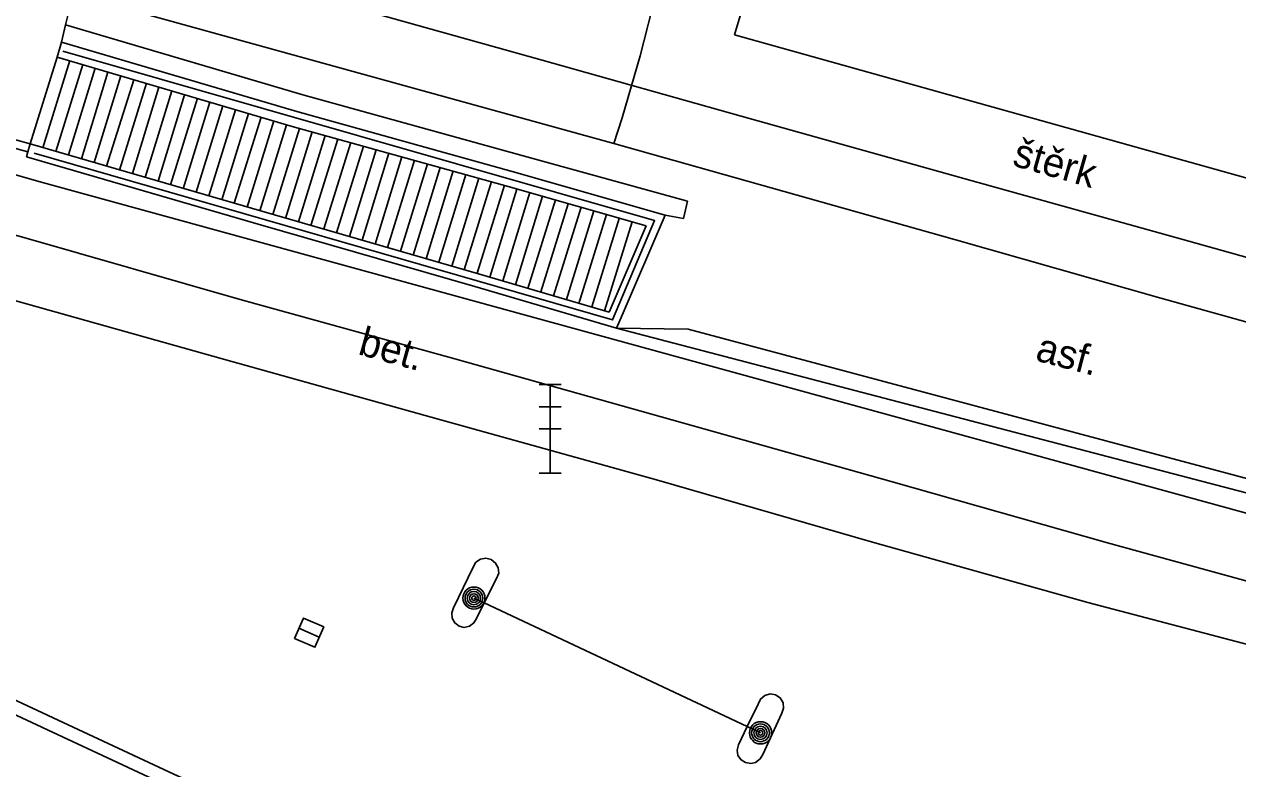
# Model space of a CAD drawing. Extents: x -600309 to -598967, y -1161267 to -1160292.
# Drawn here: x -599876.57 to -599849.18, y -1161220.83 to -1161204.03 of the extents above; entities that cross this region are included whole.
import ezdxf

# ---------------------------------------------------------------- set-up
doc = ezdxf.new("R2010")
doc.units = 0
for name, color, linetype in [('Level 11', 7, 'Continuous'), ('Level 13', 7, 'Continuous'), ('Level 25', 7, 'Continuous'), ('Level 27', 7, 'Continuous'), ('Level 33', 7, 'Continuous'), ('Level 40', 7, 'Continuous'), ('Level 7', 7, 'Continuous'), ('Level 9', 7, 'Continuous')]:
    doc.layers.add(name, color=color, linetype=linetype)

msp = doc.modelspace()

# ---------------------------------------------------------------- linework, layer by layer
at = {"layer": 'Level 11'}
for points in [[(-599943.57, -1161188.06), (-599943.4099, -1161188.13), (-599934.69, -1161190.53), (-599924.78, -1161193.29), (-599915.04, -1161195.99), (-599905.21, -1161198.73), (-599895.46, -1161201.46), (-599885.6599, -1161204.19), (-599876.44, -1161206.73)], [(-599943.62, -1161188.24), (-599939.48, -1161189.38), (-599934.7199, -1161190.69), (-599929.63, -1161192.12), (-599924.84, -1161193.46), (-599919.9, -1161194.81), (-599915.13, -1161196.14), (-599910.12, -1161197.53), (-599905.29, -1161198.87), (-599900.4099, -1161200.24), (-599895.52, -1161201.62), (-599891.36, -1161202.78), (-599885.75, -1161204.34), (-599880.31, -1161205.86), (-599876.49, -1161206.9099)], [(-599789.95, -1161232.9), (-599790.9699, -1161236.06), (-599800.96, -1161233.11), (-599809.71, -1161230.49), (-599818.68, -1161230.93), (-599828.53, -1161231.42), (-599840.03, -1161232.03), (-599849.05, -1161232.52), (-599855.12, -1161229.63), (-599865.36, -1161224.89), (-599873.32, -1161221.2199), (-599882.6599, -1161216.87), (-599894.05, -1161211.49), (-599904.05, -1161206.78), (-599911.83, -1161203.14), (-599911.7, -1161202.87)], [(-599789.95, -1161232.9), (-599790.24, -1161232.81), (-599791.17, -1161235.69), (-599800.87, -1161232.82), (-599809.67, -1161230.19), (-599818.7, -1161230.63), (-599828.55, -1161231.12), (-599840.05, -1161231.73), (-599848.99, -1161232.2199), (-599854.99, -1161229.36), (-599865.23, -1161224.62), (-599873.19, -1161220.95), (-599882.53, -1161216.6), (-599893.92, -1161211.2199), (-599903.92, -1161206.51), (-599911.7, -1161202.87)], [(-599875.64, -1161204.04), (-599875.4699, -1161203.34)], [(-599875.4699, -1161203.34), (-599863.26, -1161206.7199)], [(-599863.26, -1161206.7199), (-599863.07, -1161206.14), (-599862.67, -1161204.74), (-599862.3, -1161203.29)], [(-599860.4099, -1161203.84), (-599860.54, -1161204.27)], [(-599875.73, -1161204.43), (-599875.64, -1161204.04)], [(-599861.6, -1161208.02), (-599865.44, -1161206.96), (-599870.28, -1161205.62), (-599875.64, -1161204.04)], [(-599860.54, -1161204.27), (-599838.15, -1161210.53)], [(-599876.44, -1161206.73), (-599875.83, -1161204.77)], [(-599876.15, -1161206.82), (-599875.54, -1161204.85)], [(-599875.86, -1161206.9), (-599875.25, -1161204.94)], [(-599875.57, -1161206.98), (-599874.9699, -1161205.02)], [(-599875.28, -1161207.07), (-599874.68, -1161205.11)], [(-599874.99, -1161207.15), (-599874.39, -1161205.19)], [(-599874.71, -1161207.23), (-599874.1, -1161205.28)], [(-599874.42, -1161207.32), (-599873.81, -1161205.36)], [(-599874.13, -1161207.4), (-599873.53, -1161205.45)], [(-599873.84, -1161207.49), (-599873.24, -1161205.53)], [(-599873.55, -1161207.57), (-599872.95, -1161205.62)], [(-599873.27, -1161207.65), (-599872.6599, -1161205.7)], [(-599872.98, -1161207.74), (-599872.38, -1161205.79)], [(-599872.69, -1161207.82), (-599872.09, -1161205.87)], [(-599872.4, -1161207.9), (-599871.8, -1161205.96)], [(-599872.11, -1161207.99), (-599871.51, -1161206.04)], [(-599871.83, -1161208.07), (-599871.2199, -1161206.13)], [(-599876.1599, -1161207.6), (-599880.31, -1161206.42)], [(-599871.54, -1161208.1599), (-599870.94, -1161206.21)], [(-599871.25, -1161208.24), (-599870.65, -1161206.3)], [(-599870.96, -1161208.32), (-599870.36, -1161206.38)], [(-599870.67, -1161208.4099), (-599870.07, -1161206.46)], [(-599870.38, -1161208.49), (-599869.78, -1161206.54)], [(-599870.1, -1161208.57), (-599869.49, -1161206.62)], [(-599869.81, -1161208.65), (-599869.2, -1161206.7)], [(-599869.52, -1161208.74), (-599868.9099, -1161206.78)], [(-599869.23, -1161208.82), (-599868.63, -1161206.86)], [(-599868.94, -1161208.9), (-599868.34, -1161206.94)], [(-599838.9699, -1161213.53), (-599841.14, -1161212.95), (-599845.89, -1161211.61), (-599850.9099, -1161210.21), (-599855.57, -1161208.89), (-599863.26, -1161206.7199)], [(-599868.65, -1161208.99), (-599868.05, -1161207.02)], [(-599868.37, -1161209.07), (-599867.76, -1161207.1)], [(-599868.08, -1161209.15), (-599867.4699, -1161207.18)], [(-599867.79, -1161209.24), (-599867.18, -1161207.26)], [(-599867.5, -1161209.32), (-599866.89, -1161207.34)], [(-599867.21, -1161209.4), (-599866.6, -1161207.42)], [(-599866.92, -1161209.49), (-599866.31, -1161207.5)], [(-599846.74, -1161215.68), (-599876.1599, -1161207.6)], [(-599866.64, -1161209.57), (-599866.02, -1161207.58)], [(-599866.35, -1161209.65), (-599865.73, -1161207.6599)], [(-599866.06, -1161209.74), (-599865.45, -1161207.75)], [(-599865.77, -1161209.82), (-599865.1599, -1161207.83)], [(-599865.48, -1161209.9099), (-599864.87, -1161207.9099)], [(-599865.2, -1161209.99), (-599864.58, -1161207.99)], [(-599861.6, -1161208.02), (-599861.69, -1161208.4099), (-599862.1, -1161208.34)], [(-599864.9099, -1161210.07), (-599864.29, -1161208.08)], [(-599864.62, -1161210.1599), (-599864, -1161208.1599)], [(-599864.33, -1161210.24), (-599863.71, -1161208.24)], [(-599864.05, -1161210.33), (-599863.43, -1161208.32)], [(-599863.76, -1161210.4099), (-599863.14, -1161208.4099)], [(-599863.4699, -1161210.5), (-599862.85, -1161208.49)], [(-599881, -1161209.08), (-599876.95, -1161210.2199), (-599872.07, -1161211.59), (-599867.2, -1161212.95), (-599862.3, -1161214.31), (-599857.42, -1161215.7199), (-599852.56, -1161217.08), (-599842.77, -1161219.65)], [(-599863.2, -1161210.89), (-599861.58, -1161210.9099), (-599839.8, -1161216.73)], [(-599839.87, -1161216.99), (-599863.2, -1161210.89)], [(-599866.44, -1161216.28), (-599866.88, -1161217.2)], [(-599866.44, -1161216.28), (-599866.38, -1161216.17), (-599866.27, -1161216.1), (-599866.15, -1161216.08), (-599866.03, -1161216.11), (-599865.93, -1161216.19), (-599865.87, -1161216.3), (-599865.86, -1161216.42), (-599865.9099, -1161216.54)], [(-599865.9099, -1161216.54), (-599866.19, -1161217.09)], [(-599866.19, -1161217.09), (-599866.42, -1161216.98)], [(-599866.19, -1161217.09), (-599866.36, -1161217.44)], [(-599860.25, -1161219.88), (-599866.19, -1161217.09)], [(-599866.36, -1161217.44), (-599866.42, -1161217.54), (-599866.52, -1161217.61), (-599866.64, -1161217.64), (-599866.75, -1161217.61), (-599866.85, -1161217.54), (-599866.9099, -1161217.43), (-599866.92, -1161217.31), (-599866.88, -1161217.2)], [(-599860, -1161219.37), (-599859.95, -1161219.26), (-599859.85, -1161219.18), (-599859.73, -1161219.14), (-599859.61, -1161219.1599), (-599859.51, -1161219.23), (-599859.44, -1161219.34), (-599859.43, -1161219.46), (-599859.4699, -1161219.58)], [(-599860, -1161219.37), (-599860.25, -1161219.88)], [(-599859.9, -1161220.51), (-599859.4699, -1161219.58)], [(-599860.25, -1161219.88), (-599860.45, -1161220.29)], [(-599859.95, -1161220.02), (-599860.25, -1161219.88)], [(-599859.9, -1161220.51), (-599859.96, -1161220.61), (-599860.06, -1161220.69), (-599860.17, -1161220.71), (-599860.29, -1161220.69), (-599860.39, -1161220.63), (-599860.46, -1161220.53), (-599860.48, -1161220.4099), (-599860.45, -1161220.29)]]:
    msp.add_lwpolyline(points, dxfattribs=at)
at = {"layer": 'Level 13'}
for points in [[(-599939.98, -1161191.14), (-599935.24, -1161192.5), (-599930.2199, -1161193.87), (-599925.33, -1161195.24), (-599920.48, -1161196.58), (-599915.56, -1161197.96), (-599910.63, -1161199.32), (-599905.82, -1161200.68), (-599900.94, -1161202.06), (-599896.01, -1161203.4099), (-599891.2, -1161204.75), (-599886.26, -1161206.12), (-599881.48, -1161207.48), (-599876.58, -1161208.84), (-599871.7, -1161210.24), (-599866.85, -1161211.58), (-599861.95, -1161212.96), (-599857, -1161214.35), (-599852.12, -1161215.73), (-599847.21, -1161217.08), (-599842.49, -1161218.27)], [(-599908.81, -1161192.58), (-599904.09, -1161193.9), (-599899.19, -1161195.27), (-599894.29, -1161196.65), (-599889.4099, -1161198.01), (-599884.62, -1161199.34), (-599879.6599, -1161200.7199), (-599875.02, -1161202), (-599869.7, -1161203.49), (-599864.88, -1161204.84), (-599860.39, -1161206.1), (-599855.17, -1161207.56), (-599850.4699, -1161208.87), (-599845.4699, -1161210.27), (-599840.67, -1161211.61), (-599835.69, -1161213), (-599831.84, -1161214.03)]]:
    msp.add_lwpolyline(points, dxfattribs=at)
at = {"layer": 'Level 25'}
for centre, radius in [((-599866.42, -1161216.98), 0.25), ((-599866.42, -1161216.98), 0.2), ((-599866.42, -1161216.98), 0.15), ((-599866.42, -1161216.98), 0.1), ((-599866.42, -1161216.98), 0.05), ((-599859.95, -1161220.02), 0.25), ((-599859.95, -1161220.02), 0.2), ((-599859.95, -1161220.02), 0.15), ((-599859.95, -1161220.02), 0.1), ((-599859.95, -1161220.02), 0.05)]:
    msp.add_circle(centre, radius, dxfattribs=at)
at = {"layer": 'Level 27'}
msp.add_line((-599870.3694, -1161217.6605), (-599869.9106, -1161217.8595), dxfattribs=at)
msp.add_lwpolyline([(-599870.4688, -1161217.8899), (-599870.0101, -1161218.0888), (-599869.8112, -1161217.6301), (-599870.2699, -1161217.4312)], close=True, dxfattribs=at)
at = {"layer": 'Level 33'}
for p, q in [((-599864.95, -1161212.1599), (-599864.45, -1161212.1599)), ((-599864.7, -1161214.1599), (-599864.7, -1161212.1599)), ((-599864.95, -1161212.6599), (-599864.45, -1161212.6599)), ((-599864.95, -1161213.1599), (-599864.45, -1161213.1599)), ((-599864.95, -1161214.1599), (-599864.45, -1161214.1599))]:
    msp.add_line(p, q, dxfattribs=at)
at = {"layer": 'Level 7'}
for points in [[(-599875.83, -1161204.77), (-599875.73, -1161204.43)], [(-599862.1, -1161208.34), (-599865.56, -1161207.35), (-599870.42, -1161206), (-599875.73, -1161204.43)], [(-599862.53, -1161208.58), (-599865.65, -1161207.69), (-599870.52, -1161206.34), (-599875.83, -1161204.77)], [(-599876.52, -1161207.02), (-599876.49, -1161206.9099)], [(-599876.49, -1161206.9099), (-599876.44, -1161206.73)], [(-599876.44, -1161206.73), (-599871.21, -1161208.25), (-599866.32, -1161209.6599), (-599863.37, -1161210.53)], [(-599876.52, -1161207.02), (-599871.29, -1161208.54), (-599866.4, -1161209.95), (-599863.2, -1161210.89)], [(-599863.2, -1161210.89), (-599863.0719, -1161210.5931), (-599862.1, -1161208.34)], [(-599863.37, -1161210.53), (-599862.53, -1161208.58)]]:
    msp.add_lwpolyline(points, dxfattribs=at)
at = {"layer": 'Level 9'}
msp.add_lwpolyline([(-599876.35, -1161206.94), (-599863.29, -1161210.7), (-599862.34, -1161208.46), (-599875.7, -1161204.64)], dxfattribs=at)

# ---------------------------------------------------------------- texts
at = {"layer": 'Level 40'}
for s, rotation, p in [('štěrk', 344.04, (-599854.29, -1161207.21)), ('bet.', 344.44, (-599869.06, -1161211.4699)), ('asf.', 345.2, (-599853.77, -1161211.61))]:
    msp.add_text(s, height=0.65, rotation=rotation, dxfattribs=at).set_placement(p)

doc.saveas('drawing.dxf')
